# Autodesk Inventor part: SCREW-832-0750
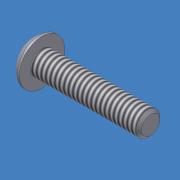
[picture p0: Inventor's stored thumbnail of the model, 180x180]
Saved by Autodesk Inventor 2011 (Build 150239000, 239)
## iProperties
Created: 2007-08
Part Number: SCREW-832-0750
Material: Stainless Steel
Document SubType Name: Modeling
Density: 8.08 g/cm^3
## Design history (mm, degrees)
feature "Base1"
thread "Thread1" dims "d0" = 25.4, "d1" = 0
body "Solid1"
